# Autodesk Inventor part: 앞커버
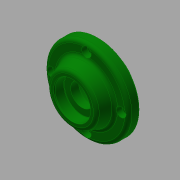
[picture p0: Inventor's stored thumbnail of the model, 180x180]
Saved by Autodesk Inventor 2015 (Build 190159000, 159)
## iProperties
Created: 2017-08
Part Number: 앞커버
Material: 알루미늄 6061
Document SubType Name: Modeling
Designer: mduedu
Density: 1 g/cm^3
Appearance: 진녹색
Author: mduedu
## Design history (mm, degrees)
sketch "스케치1"
  geometry: C1 r 35 at (0, 0); 1 further point
  constraints: 1 centre point, 1 coincident
  dimensions: "d0" = 70 diameter of C1
extrude "돌출1" new body sketch "스케치1" distance "d1" = 10; taper "d2" = 0 deg
sketch "스케치2"
  geometry: C1 r 24 at (0, 0); 1 further point
  constraints: 1 centre point, 1 coincident
  dimensions: "d3" = 48 diameter of C1
node "작업 평면1"
sketch "스케치3"
  geometry: C1 r 20 at (0, 0); 1 further point
  constraints: 1 centre point, 1 coincident
  dimensions: "d5" = 40 diameter of C1
feature "로프트1" sketch "스케치3" dims "d6" = 0, "d7" = 90 deg, "d8" = 0, "d9" = 90 deg
sketch "스케치4"
  geometry: C1 r 24 at (0, 0) reference; 1 further point
extrude "돌출2" join sketch "스케치4" distance "d10" = 8; taper "d11" = 0 deg
hole "구멍1" diameter "d14" = 40; stored, may be unused: countersink angle "d18" = 90 deg, drill point angle "d20" = 0 deg; dims "d12" = 10, "d13" = 10, "d15" = 6, "d16" = 4, "d17" = 2, "d19" = 12
hole "구멍2" diameter "d23" = 34; stored, may be unused: countersink angle "d27" = 90 deg, drill point angle "d29" = 0 deg; dims "d21" = 10, "d22" = 10, "d24" = 6, "d25" = 4, "d26" = 2, "d28" = 3
hole "구멍3" diameter "d32" = 19; stored, may be unused: countersink angle "d36" = 90 deg, drill point angle "d38" = 0 deg; dims "d30" = 10, "d31" = 10, "d33" = 6, "d34" = 4, "d35" = 2, "d37" = 3
chamfer "모따기1" distance "d39" = 1; stored, may be unused: second distance "d40" = 2, angle "d41" = 45 deg
sketch "스케치5"
  geometry: C1 r 15 at (0, 0); 1 further point
  constraints: 1 centre point, 1 coincident
  dimensions: "d42" = 30 diameter of C1
extrude "돌출3" cut sketch "스케치5" distance "d43" = 8.3; taper "d44" = 0 deg
chamfer "모따기2" distance "d47" = 0.8; stored, may be unused: second distance "d48" = 2, angle "d49" = 30 deg
fillet "모깎기1" dims "d50" = 0.3
fillet "모깎기2" dims "d51" = 0.3
fillet "모깎기3" dims "d52" = 3
sketch "스케치6" dims "d53" = 58
  geometry: 6 further points
  constraints: 2 vertical alignment, 1 coincident, 7 other
  dimensions: "d56" = 360 deg dimension on point (0, 0) point (0, 29) (derived)
sketch "스케치9"
  geometry: 4 further points
  constraints: 4 other
hole "구멍6" sketch "스케치9" at (-29, 0), (0, -29), (29, 0), (0, 29) diameter "d72" = 4.5; stored, may be unused: countersink angle "d76" = 90 deg, drill point angle "d78" = 0 deg; dims "d73" = 6, "d74" = 8, "d75" = 4.6, "d77" = 8
fillet "모깎기4" dims "d79" = 3
fillet "모깎기5" dims "d80" = 3
fillet "모깎기6" dims "d81" = 3
chamfer "모따기3" distance "d82" = 1; stored, may be unused: second distance "d83" = 2, angle "d84" = 30 deg
node "솔리드1"
other parameters: "d4" = 12
